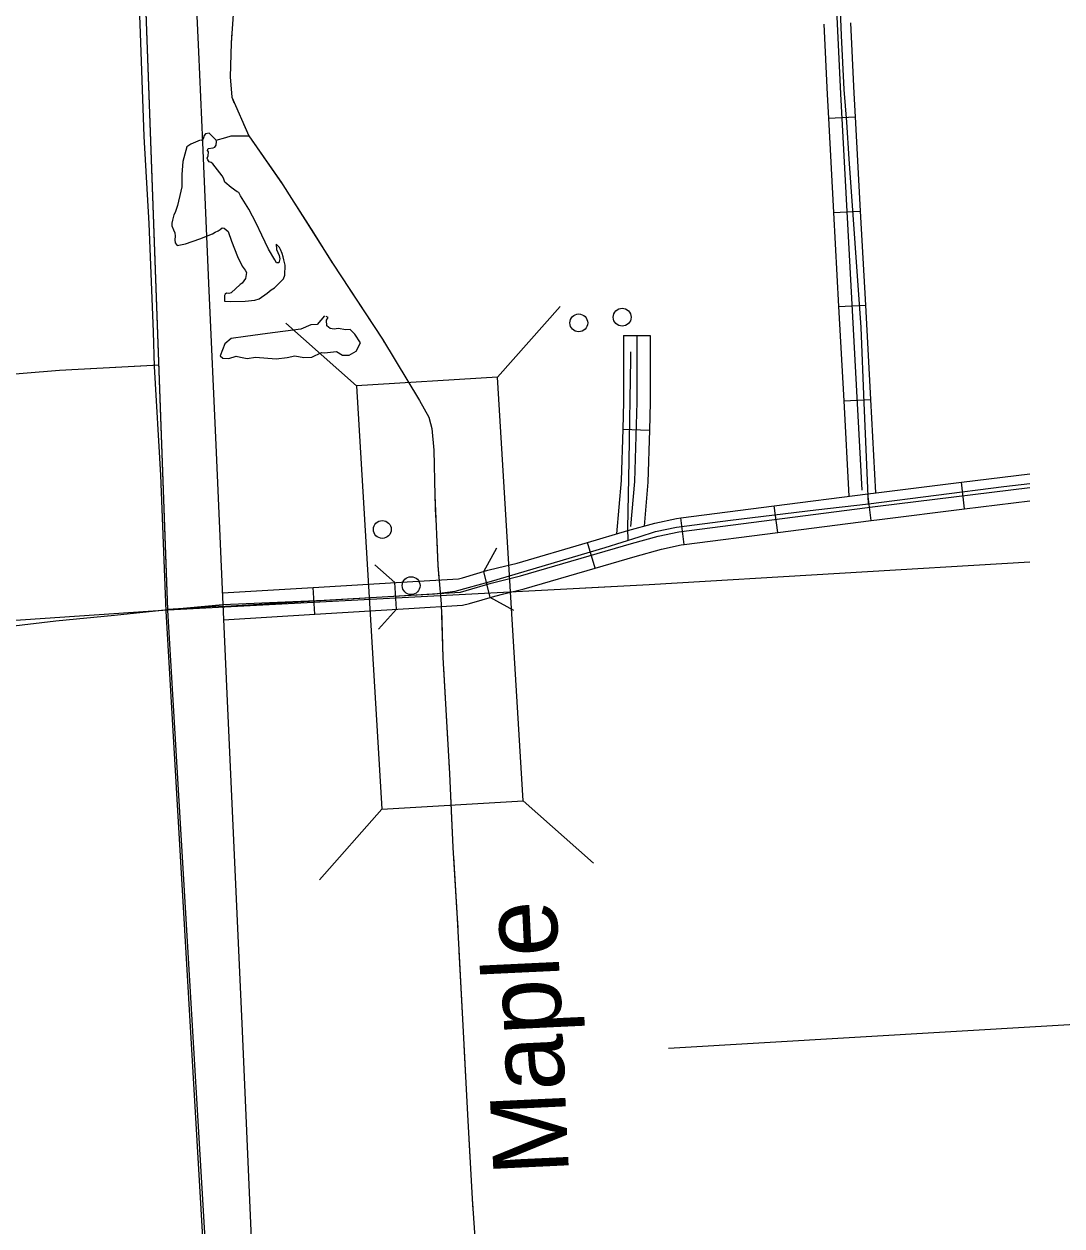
# Model space of a CAD drawing. Extents: x 646058 to 725608, y 1473014 to 1561048.
# Drawn here: x 665563 to 668470, y 1549300 to 1552665 of the extents above; entities that cross this region are included whole.
import ezdxf

# ---------------------------------------------------------------- set-up
doc = ezdxf.new("R2010")
doc.units = 0
doc.layers.add('Default', color=7, linetype='Continuous')

msp = doc.modelspace()

# ---------------------------------------------------------------- linework, layer by layer
at = {"layer": 'Default'}
for p, q in [((667816, 1552401), (667890.8, 1552405.1)), ((667830.2, 1552137.4), (667905.1, 1552141.5)), ((666888.9, 1551676.3), (667064, 1551873.9)), ((667844.4, 1551873.8), (667919.3, 1551877.9)), ((666493.6, 1551652.5), (666296, 1551827.5)), ((667241.9, 1551793.1), (667316.9, 1551793.1)), ((667858.6, 1551610.2), (667933.5, 1551614.2)), ((667239.5, 1551530.4), (667314.4, 1551528)), ((668197.3, 1551307.5), (668188.2, 1551382)), ((667935.5, 1551275.3), (667926, 1551349.7)), ((667673.7, 1551241.6), (667664.1, 1551316)), ((667411.8, 1551207.9), (667402.3, 1551282.3)), ((667162.5, 1551141.9), (667141.4, 1551213.9)), ((666868.6, 1551059.6), (666850.6, 1551132.4)), ((666605.6, 1551026.6), (666601, 1551101.4)), ((666377.2, 1551012.8), (666372.7, 1551087.7)), ((666565.2, 1550466.6), (666390.1, 1550269)), ((666960.4, 1550490.5), (667158, 1550315.4))]:
    msp.add_line(p, q, dxfattribs=at)
for points in [[(662560.5, 1554096.2), (663187, 1554136.5), (663575.2, 1554161.8), (664495.7, 1554221.9), (665174.2, 1554262.2), (665817.1, 1554300.4), (665974, 1554309.7), (665988.7, 1553980.9), (666006.9, 1553572.2), (666025.3, 1553160.3), (666037.4, 1552889.3), (666050.9, 1552586.8), (666062.2, 1552333.1), (666079.8, 1551939.6), (666100.9, 1551465.6), (666118, 1551082), (666129.2, 1550831.7), (666173.2, 1549845.3), (666198.1, 1549286)], [(665965.9, 1551024.1), (665870.1, 1553650.2), (665836.1, 1554301.5)], [(666114.9, 1551035.6), (665965.9, 1551026), (665870.1, 1553650.2), (665836.1, 1554301.5)], [(665974, 1554309.7), (665988.7, 1553980.9), (666006.9, 1553572.2), (666025.3, 1553160.3), (666037.4, 1552889.3), (666050.9, 1552586.8), (666062.2, 1552333.1), (666079.8, 1551939.6), (666100.9, 1551465.6), (666118, 1551082), (666129.2, 1550831.7), (666173.2, 1549845.3), (666198.1, 1549286), (666212.8, 1548957.6), (666229, 1548593.2)], [(665851.2, 1553638.1), (665863.7, 1553214.7), (665887, 1552665.6), (665898.6, 1552349.9), (665912.2, 1552106.6), (665924.1, 1551802.9), (665926.9, 1551706.1)], [(665965.9, 1551024.1), (665870.1, 1553650.2)], [(666261.2, 1553591.2), (666260.8, 1553578.1), (666252.1, 1553468.2), (666220.8, 1553203.2), (666201.2, 1553063.4), (666184.4, 1552968.7), (666166.9, 1552800.5), (666149.5, 1552705.9), (666142.9, 1552611.9), (666140, 1552517.3), (666144.4, 1552459.8), (666192.2, 1552352.3), (666287.8, 1552214.4), (666428.3, 1551993.1), (666566.6, 1551782.6), (666670.7, 1551611.5), (666696.2, 1551564.2), (666704.9, 1551532.9), (666710.7, 1551471.8), (666712.9, 1551345.1), (666721.6, 1551149.2), (666724.8, 1551113.3)], [(668379.5, 1553160.9), (667871, 1553141.9), (667839.3, 1553117.2), (667828.7, 1553078.5), (667832.2, 1552842.5), (667849.8, 1552469.3), (667909.7, 1551360)], [(667928.3, 1551321.8), (667916.1, 1551604.6), (667907.7, 1551815.5), (667874.2, 1552287.5), (667867, 1552390.5), (667859.8, 1552481.6), (667852.6, 1552632.5), (667849, 1552727.2), (667837, 1552769.1), (667837, 1552789.5), (667847.8, 1552830.2), (667843, 1552977.6), (667838.2, 1553104.6), (667850.2, 1553121.3), (667879, 1553138.1), (667904.1, 1553144.1), (667954.4, 1553148.9), (668039.5, 1553151.3), (668164, 1553158.5), (668279, 1553164.5), (668379.5, 1553171.7)], [(666149.5, 1552705.9), (666142.9, 1552611.9), (666140, 1552517.3), (666144.4, 1552459.8), (666192.2, 1552352.3), (666287.8, 1552214.4), (666428.3, 1551993.1), (666566.6, 1551782.6), (666670.7, 1551611.5), (666696.2, 1551564.2), (666704.9, 1551532.9), (666710.7, 1551471.8), (666712.9, 1551345.1), (666721.6, 1551149.2), (666731.1, 1551042.2), (666735.5, 1550891.5), (666754.4, 1550566.7), (666763.8, 1550359.2), (666776.2, 1550160.5), (666790.8, 1549878.7), (666804.6, 1549612.2), (666817.7, 1549375.6), (666839.6, 1549064)], [(667803.1, 1552665), (667812.4, 1552467.4), (667816, 1552401)], [(667878, 1552668.5), (667887.3, 1552471.2), (667890.8, 1552405.1)], [(666145, 1552641.9), (666142.9, 1552611.9), (666140, 1552517.3), (666144.4, 1552459.8), (666150.7, 1552445.5)], [(666177.5, 1552385.2), (666192.2, 1552352.3), (666284.5, 1552219.2)], [(667816, 1552401), (667830.2, 1552137.4)], [(667890.8, 1552405.1), (667905.1, 1552141.5)], [(666055.8, 1552339.6), (666029.5, 1552328.9), (666018.8, 1552321.1), (666007.1, 1552280.2), (666005.1, 1552244.1), (666005.1, 1552236.3), (666005.1, 1552226.6), (666005.1, 1552217.8), (666004.2, 1552209), (666002.2, 1552197.3), (665992.5, 1552157.4), (665989.5, 1552148.6), (665985.6, 1552136.9), (665982.7, 1552131.1), (665978.8, 1552115.5), (665976.9, 1552107.7), (665976.9, 1552099.9), (665981.7, 1552089.2), (665984.7, 1552080.4), (665985.6, 1552070.7), (665984.7, 1552060.9), (665985.6, 1552052.1), (665991.5, 1552045.3), (666014.9, 1552049.2), (666054.8, 1552063.8), (666090.9, 1552077.5), (666097.7, 1552082.4), (666106.5, 1552086.3), (666112.3, 1552090.2), (666117.2, 1552094.1), (666123, 1552093.1), (666134.7, 1552084.3), (666143.5, 1552057), (666161, 1552014.1), (666173.7, 1551986.9), (666182.4, 1551976.1), (666185.4, 1551969.3), (666183.4, 1551952.8), (666173.7, 1551939.1), (666167.8, 1551936.2), (666142.5, 1551912.8), (666136.7, 1551910.8), (666129.8, 1551911.8), (666125.9, 1551908.9), (666124, 1551905), (666124, 1551889.4), (666141.5, 1551888.4), (666182.4, 1551889.4), (666208.8, 1551892.3), (666221.4, 1551895.3), (666243.8, 1551911.8), (666254.5, 1551920.6), (666264.3, 1551926.4), (666270.1, 1551932.3), (666289.6, 1551951.8), (666293.5, 1551961.5), (666294.5, 1551989.8), (666290.6, 1552004.4), (666288.6, 1552013.2), (666285.7, 1552022.9), (666280.8, 1552033.6), (666277.9, 1552039.5), (666269.2, 1552048.3), (666270.1, 1552033.6), (666273.1, 1552025.8), (666277, 1552017.1), (666278.9, 1552007.3), (666276, 1551996.6), (666270.1, 1551996.6), (666265.3, 1552004.4), (666247.7, 1552034.6), (666229.2, 1552073.6), (666212.7, 1552107.7), (666192.2, 1552146.7), (666168.8, 1552183.7), (666163.9, 1552193.4), (666160, 1552195.4), (666142.5, 1552207.1), (666125, 1552222.7), (666123, 1552227.6), (666121.1, 1552233.4), (666117.2, 1552240.2), (666091.8, 1552273.4), (666087, 1552277.3), (666081.1, 1552279.2), (666077.2, 1552285.1), (666075.3, 1552289.9), (666078.2, 1552295.8), (666079.2, 1552307.5), (666076.3, 1552311.4), (666078.2, 1552316.2), (666092.8, 1552318.2), (666096.7, 1552320.1), (666100.6, 1552326), (666101.6, 1552335.7), (666100.6, 1552339.6), (666081.1, 1552359.1), (666071.4, 1552357.2), (666067.5, 1552353.3), (666065.5, 1552346.4), (666063.6, 1552341.6)], [(666221.4, 1551895.3), (666243.8, 1551911.8), (666254.5, 1551920.6), (666264.3, 1551926.4), (666270.1, 1551932.3), (666289.6, 1551951.8), (666293.5, 1551961.5), (666294.5, 1551989.8), (666290.6, 1552004.4), (666288.6, 1552013.2), (666285.7, 1552022.9), (666280.8, 1552033.6), (666277.9, 1552039.5), (666269.2, 1552048.3), (666270.1, 1552033.6), (666273.1, 1552025.8), (666277, 1552017.1), (666278.9, 1552007.3), (666276, 1551996.6), (666270.1, 1551996.6), (666265.3, 1552004.4), (666247.7, 1552034.6), (666229.2, 1552073.6), (666212.7, 1552107.7), (666192.2, 1552146.7), (666168.8, 1552183.7), (666163.9, 1552193.4), (666160, 1552195.4), (666142.5, 1552207.1), (666125, 1552222.7), (666123, 1552227.6), (666121.1, 1552233.4), (666117.2, 1552240.2), (666091.8, 1552273.4), (666087, 1552277.3), (666081.1, 1552279.2), (666077.2, 1552285.1), (666075.3, 1552289.9), (666078.2, 1552295.8), (666079.2, 1552307.5), (666076.3, 1552311.4), (666078.2, 1552316.2), (666092.8, 1552318.2), (666096.7, 1552320.1), (666100.6, 1552326), (666101.6, 1552335.7), (666100.6, 1552339.6), (666081.1, 1552359.1), (666071.4, 1552357.2), (666067.5, 1552353.3), (666065.5, 1552346.4), (666063.6, 1552341.6)], [(666100.6, 1552339.6), (666127.9, 1552347.4), (666142.5, 1552352.3), (666180.5, 1552352.3), (666192.2, 1552352.3)], [(666100.6, 1552339.6), (666127.9, 1552347.4), (666142.5, 1552352.3), (666180.5, 1552352.3), (666192.2, 1552352.3)], [(666055.8, 1552339.6), (666029.5, 1552328.9), (666018.8, 1552321.1), (666007.1, 1552280.2), (666005.1, 1552244.1), (666005.1, 1552236.3), (666005.1, 1552226.6), (666005.1, 1552217.8), (666004.2, 1552209), (666002.2, 1552197.3), (665992.5, 1552157.4), (665989.5, 1552148.6), (665985.6, 1552136.9), (665982.7, 1552131.1), (665978.8, 1552115.5), (665976.9, 1552107.7), (665976.9, 1552099.9), (665981.7, 1552089.2), (665984.7, 1552080.4), (665985.6, 1552070.7), (665984.7, 1552060.9), (665985.6, 1552052.1), (665991.5, 1552045.3), (666014.9, 1552049.2), (666054.8, 1552063.8), (666090.9, 1552077.5), (666097.7, 1552082.4), (666106.5, 1552086.3), (666112.3, 1552090.2), (666117.2, 1552094.1), (666123, 1552093.1), (666134.7, 1552084.3), (666143.5, 1552057), (666161, 1552014.1), (666173.7, 1551986.9), (666182.4, 1551976.1), (666185.4, 1551969.3), (666183.4, 1551952.8), (666173.7, 1551939.1), (666167.8, 1551936.2), (666142.5, 1551912.8), (666136.7, 1551910.8), (666129.8, 1551911.8), (666125.9, 1551908.9), (666124, 1551905), (666124, 1551889.4), (666141.5, 1551888.4), (666182.4, 1551889.4), (666208.8, 1551892.3), (666221.4, 1551895.3)], [(666063.6, 1552341.6), (666057.7, 1552338.6)], [(666063.6, 1552341.6), (666057.7, 1552338.6)], [(666320, 1552163.6), (666373.1, 1552080)], [(667905.1, 1552141.5), (667919.3, 1551877.9)], [(667830.2, 1552137.4), (667844.4, 1551873.8)], [(666373.1, 1552080), (666426.1, 1551996.4)], [(666462.3, 1551941.2), (666566.6, 1551782.6), (666570.8, 1551775.6)], [(667844.4, 1551873.8), (667858.6, 1551610.2)], [(667919.3, 1551877.9), (667933.5, 1551614.2)], [(666404.6, 1551848.5), (666384.1, 1551824.1), (666365.6, 1551823.1), (666338.3, 1551810.5), (666244.8, 1551798.8), (666183.4, 1551790), (666142.5, 1551784.2), (666125, 1551769.5), (666112.3, 1551736.4), (666119.1, 1551729.6), (666136.7, 1551728.6), (666157.1, 1551735.4), (666168.8, 1551732.5), (666187.3, 1551728.6), (666210.7, 1551732.5), (666269.2, 1551727.6), (666299.4, 1551731.5), (666320.8, 1551736.4), (666346.1, 1551731.5), (666368.5, 1551732.5), (666395.8, 1551745.2), (666404.6, 1551744.2), (666437.7, 1551748.1), (666454.3, 1551738.4), (666473.8, 1551738.4), (666493.2, 1551749.1), (666504.9, 1551772.5), (666489.3, 1551796.8), (666475.7, 1551809.5), (666464, 1551808.5), (666442.6, 1551812.4), (666430.9, 1551810.5), (666420.2, 1551812.4), (666410.4, 1551820.2), (666409.5, 1551835.8), (666414.3, 1551843.6), (666408.5, 1551846.5)], [(666404.6, 1551848.5), (666384.1, 1551824.1), (666365.6, 1551823.1), (666338.3, 1551810.5), (666244.8, 1551798.8), (666183.4, 1551790), (666142.5, 1551784.2), (666125, 1551769.5), (666112.3, 1551736.4), (666119.1, 1551729.6), (666136.7, 1551728.6), (666157.1, 1551735.4), (666168.8, 1551732.5), (666187.3, 1551728.6), (666210.7, 1551732.5), (666269.2, 1551727.6), (666299.4, 1551731.5), (666320.8, 1551736.4), (666346.1, 1551731.5), (666368.5, 1551732.5), (666395.8, 1551745.2), (666404.6, 1551744.2), (666437.7, 1551748.1), (666454.3, 1551738.4), (666473.8, 1551738.4), (666493.2, 1551749.1), (666504.9, 1551772.5), (666489.3, 1551796.8), (666475.7, 1551809.5), (666464, 1551808.5), (666442.6, 1551812.4), (666430.9, 1551810.5), (666420.2, 1551812.4), (666410.4, 1551820.2), (666409.5, 1551835.8), (666414.3, 1551843.6), (666408.5, 1551846.5)], [(667241.9, 1551793.1), (667241.9, 1551607.1), (667239.5, 1551530.4)], [(667279.4, 1551793.1), (667279.4, 1551606.5), (667272.4, 1551384.6), (667261.8, 1551257.9)], [(667316.9, 1551793.1), (667316.9, 1551605.9), (667314.4, 1551528)], [(667254.6, 1551219.7), (667253.7, 1551252.4), (667257.3, 1551441.7), (667262.1, 1551728), (667262.1, 1551747.2)], [(664298.5, 1551614.7), (664619, 1551634.8), (664882.7, 1551647.8), (665050.4, 1551656.7), (665247.9, 1551672.8), (665468.3, 1551680.1), (665662.2, 1551695.6), (665940.9, 1551710.5)], [(664298.5, 1551614.7), (664619, 1551634.8), (664882.7, 1551647.8), (665050.4, 1551656.7), (665247.9, 1551672.8), (665468.3, 1551680.1), (665662.2, 1551695.6), (665924.6, 1551709.6)], [(665926.9, 1551706.1), (665945.1, 1551402.2), (665960.1, 1551021.7)], [(666605.2, 1551719.2), (666670.7, 1551611.5), (666696.2, 1551564.2), (666701, 1551546.7)], [(667858.6, 1551610.2), (667873.1, 1551342.9)], [(667933.5, 1551614.2), (667947.6, 1551352.5)], [(667239.5, 1551530.4), (667234.9, 1551386.8), (667222.5, 1551237.7)], [(667314.4, 1551528), (667309.8, 1551382.5), (667299.6, 1551259.2)], [(666709.8, 1551481.5), (666710.7, 1551471.8), (666712.9, 1551345.1), (666715.6, 1551283.6)], [(668188.2, 1551382), (668379.5, 1551405.4)], [(666111.4, 1551034.3), (666784.9, 1551074.9), (666800.8, 1551078.8), (666871.3, 1551099.4), (666953.3, 1551119.8), (667264.3, 1551210.8), (667338.8, 1551231), (667396.5, 1551243.8), (667954.3, 1551315.6), (668379.5, 1551367.6)], [(666119.9, 1551039.9), (666402.9, 1551051.9), (666712.8, 1551070), (666770, 1551077), (666872.3, 1551105.1), (667190.2, 1551199.4), (667285.5, 1551229.5), (667331.6, 1551244.5), (667389.8, 1551256.6), (667541.2, 1551275.6), (667780.9, 1551304.7), (667928.3, 1551321.8), (668307.4, 1551369.9), (668379.5, 1551378.8)], [(667926, 1551349.7), (667949.6, 1551352.8), (668188.2, 1551382)], [(667664.1, 1551316), (667926, 1551349.7)], [(667402.3, 1551282.3), (667664.1, 1551316)], [(667935.5, 1551275.3), (667959, 1551278.3), (668197.3, 1551307.5)], [(668197.3, 1551307.5), (668379.5, 1551329.9)], [(667141.4, 1551213.9), (667254.1, 1551246.9), (667329.8, 1551267.4), (667390, 1551280.8), (667402.3, 1551282.3)], [(667673.7, 1551241.6), (667935.5, 1551275.3)], [(667411.8, 1551207.9), (667673.7, 1551241.6)], [(666718.6, 1551217.7), (666721.6, 1551149.2), (666724.8, 1551113.3)], [(666850.6, 1551132.4), (666886.6, 1551198.2)], [(666888.9, 1551142.4), (666943.5, 1551156), (667141.4, 1551213.9)], [(667162.5, 1551141.9), (667274.4, 1551174.7), (667347.8, 1551194.6), (667403, 1551206.8), (667411.8, 1551207.9)], [(668379.5, 1551158.1), (667313.4, 1551094.6), (665965.9, 1551024.1)], [(666544.9, 1551151.2), (666601, 1551101.4)], [(666636.2, 1551103.5), (666779.3, 1551112.2), (666791.1, 1551115), (666861.5, 1551135.6), (666888.9, 1551142.4)], [(666907, 1551069.6), (666963.1, 1551083.5), (667162.5, 1551141.9)], [(668379.5, 1551158.1), (667313.4, 1551094.6), (667135.7, 1551085.3)], [(666372.7, 1551087.7), (666636.2, 1551103.5)], [(666118.5, 1551072.3), (666372.7, 1551087.7)], [(666640.7, 1551028.7), (666790.4, 1551037.7), (666810.4, 1551042.6), (666881.1, 1551063.2), (666907, 1551069.6)], [(664324.1, 1550906.6), (664388.9, 1550906.2), (664719.4, 1550922.6), (665245.8, 1550958.5), (665518.5, 1550978.6), (665651.5, 1550994.4), (665816.2, 1551010.5), (665957.9, 1551025.1), (666119.9, 1551039.9)], [(666934.4, 1551023.5), (666868.6, 1551059.6)], [(665965.9, 1551024.1), (663352, 1550847.2)], [(664324.1, 1550906.6), (664388.9, 1550906.2), (664719.4, 1550922.6), (665245.8, 1550958.5), (665518.5, 1550978.6), (665651.5, 1550994.4), (665816.2, 1551010.5), (665965.9, 1551026)], [(665960.1, 1551021.7), (666075.8, 1549044.8)], [(665960.1, 1551021.7), (666075.8, 1549044.8)], [(666123, 1548368.2), (665965.9, 1551024.1)], [(666123, 1548368.2), (665965.9, 1551024.1)], [(666121.8, 1550997.4), (666377.2, 1551012.8)], [(666377.2, 1551012.8), (666640.7, 1551028.7)], [(666605.6, 1551026.6), (666555.8, 1550970.4)], [(666731.6, 1551025.5), (666735.5, 1550891.5), (666754.4, 1550566.7), (666763.8, 1550359.2), (666776.2, 1550160.5), (666790.8, 1549878.7), (666804.6, 1549612.2), (666817.7, 1549375.6), (666839.6, 1549064), (666849, 1548908.2)], [(666731.6, 1551025.5), (666734.4, 1550926.5)], [(666737.3, 1550860.6), (666748.8, 1550663)], [(666752.6, 1550597.1), (666754.4, 1550566.7), (666762, 1550399.3)], [(666765.5, 1550333.4), (666776.2, 1550160.5), (666777.5, 1550135.8)], [(666780.9, 1550069.8), (666790.8, 1549878.7), (666791.1, 1549872.1)], [(667367.9, 1549798), (668680.3, 1549875), (669318.5, 1549919.9)], [(666794.5, 1549806.2), (666804.6, 1549612.2), (666804.8, 1549608.5)], [(666808.5, 1549542.6), (666813.9, 1549443.7)], [(666813.9, 1549443.7), (666817.7, 1549375.6), (666819.9, 1549344.9)]]:
    msp.add_lwpolyline(points, dxfattribs=at)
msp.add_lwpolyline([(666493.6, 1551652.5), (666565.2, 1550466.6), (666960.4, 1550490.5), (666888.9, 1551676.3)], close=True, dxfattribs=at)
for centre in [(667116.5, 1551828.3), (667238.1, 1551844.2), (666566.1, 1551250.1), (666646.8, 1551092.7)]:
    msp.add_circle(centre, 25, dxfattribs=at)

# ---------------------------------------------------------------- texts
msp.add_text('Maple', height=211.2, rotation=92.7111, dxfattribs=at).set_placement((667089.1, 1549446.8))

doc.saveas('drawing.dxf')
